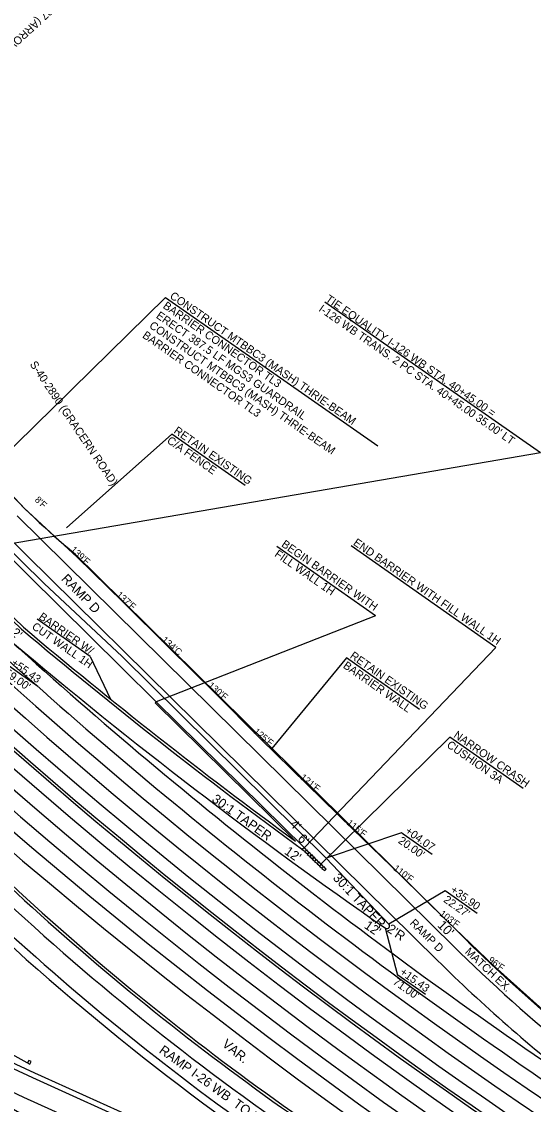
# Model space of a CAD drawing. Extents: x 1966090 to 1975830, y 788086 to 801233.
# Drawn here: x 1971783 to 1972167, y 795066 to 795878 of the extents above; entities that cross this region are included whole.
import ezdxf

# ---------------------------------------------------------------- set-up
doc = ezdxf.new("R2010")
doc.units = 0
for name, color, linetype in [('BR_PRESTRESSED BEAM', 7, 'Continuous'), ('BR_PROPOSED_DRAINAGE', 7, 'Continuous'), ('BR_REBAR', 7, 'Continuous'), ('RD_EX_Driveway_txCode', 7, 'Continuous'), ('RD_EX_RW_TX', 7, 'Continuous'), ('RD_EX_SU_Gas', 7, 'Continuous'), ('RD_EX_TX_BldgApp_ELEV', 7, 'Continuous'), ('RD_PD_PaveShd', 7, 'Continuous'), ('RD_Sketch6', 7, 'Continuous'), ('RD_Sketch8', 7, 'Continuous'), ('RD_Sketch9', 7, 'Continuous')]:
    doc.layers.add(name, color=color, linetype=linetype)

msp = doc.modelspace()

# ---------------------------------------------------------------- linework, layer by layer
at = {"layer": 'BR_PRESTRESSED BEAM'}
for p, q in [((1971761.39, 795488.77), (1971857.56, 795393.97)), ((1971857.56, 795393.97), (1971883.91, 795367.99)), ((1971754.15, 795115.72), (1971789.19, 795096.44)), ((1971788.4, 795099.15), (1971787.44, 795097.4)), ((1971787.44, 795097.4), (1971789.19, 795096.44)), ((1971790.16, 795098.19), (1971788.4, 795099.15)), ((1971789.19, 795096.44), (1971790.16, 795098.19))]:
    msp.add_line(p, q, dxfattribs=at)
msp.add_arc((1974992.33, 801056.5), 6801.99, 241.404455, 242.138411, dxfattribs=at)
at = {"layer": 'BR_PROPOSED_DRAINAGE'}
for p, q in [((1971750.82, 795549.37), (1971784.46, 795513.22)), ((1971784.46, 795513.22), (1971824.63, 795476.36)), ((1971824.63, 795476.36), (1971859.04, 795442.54)), ((1971859.04, 795442.54), (1971893.38, 795408.54)), ((1971893.38, 795408.54), (1971927.96, 795374.68)), ((1971927.96, 795374.68), (1971962.17, 795340.2)), ((1971962.17, 795340.2), (1971996.9, 795306.17)), ((1971996.9, 795306.17), (1972031.75, 795272.09)), ((1972031.75, 795272.09), (1972066.86, 795238.09)), ((1972066.86, 795238.09), (1972101.92, 795203.77)), ((1972101.92, 795203.77), (1972137.41, 795169.72)), ((1972137.41, 795169.72), (1972174.03, 795136.99))]:
    msp.add_line(p, q, dxfattribs=at)
at = {"layer": 'BR_REBAR'}
for p, q in [((1971883.91, 795367.99), (1971883.12, 795367.19)), ((1971883.12, 795367.19), (1971988.43, 795263.39)), ((1971883.91, 795367.99), (1971994.91, 795258.58))]:
    msp.add_line(p, q, dxfattribs=at)
for centre, radius, start, end in [((1974398.08, 798103.05), 3745.03, 220.92379, 225.70896), ((1974398.08, 798103.05), 3743.03, 220.92379, 225.70786), ((1974194.95, 798281.36), 3740.57, 229.84701, 233.95222), ((1974194.95, 798281.36), 3738.57, 229.84811, 233.82837)]:
    msp.add_arc(centre, radius, start, end, dxfattribs=at)
at = {"layer": 'RD_EX_SU_Gas'}
for radius, start, end in [(3784.72, 216.39766, 236.97136), (3796.72, 216.39766, 236.97136), (3842.72, 216.39766, 244.09898), (3854.72, 216.39766, 243.9112), (3866.72, 216.9932, 243.9112), (3772.72, 227.89927, 236.25939)]:
    msp.add_arc((1974296, 798203.94), radius, start, end, dxfattribs=at)
at = {"layer": 'RD_EX_TX_BldgApp_ELEV'}
for p, q in [((1971995.02, 795258.7), (1971993.5, 795257.12)), ((1971993.5, 795257.12), (1971995.59, 795255.61)), ((1971996.6, 795256.66), (1971995.02, 795258.7)), ((1971996.86, 795256.92), (1971995.34, 795255.35)), ((1971995.59, 795255.61), (1971996.6, 795256.66)), ((1971998.44, 795254.88), (1971996.86, 795256.92)), ((1971995.34, 795255.35), (1971997.43, 795253.83)), ((1971998.7, 795255.15), (1971997.17, 795253.57)), ((1971997.17, 795253.57), (1971999.26, 795252.06)), ((1971997.43, 795253.83), (1971998.44, 795254.88)), ((1972000.28, 795253.11), (1971998.7, 795255.15)), ((1972000.53, 795253.37), (1971999.01, 795251.8)), ((1971999.01, 795251.8), (1972001.1, 795250.28)), ((1971999.26, 795252.06), (1972000.28, 795253.11)), ((1972002.12, 795251.33), (1972000.53, 795253.37)), ((1972002.37, 795251.59), (1972000.85, 795250.02)), ((1972000.85, 795250.02), (1972002.94, 795248.51)), ((1972001.1, 795250.28), (1972002.12, 795251.33)), ((1972001.61, 795250.81), (1972001.61, 795250.81)), ((1972003.95, 795249.56), (1972002.37, 795251.59)), ((1972004.21, 795249.82), (1972002.69, 795248.24)), ((1972002.69, 795248.24), (1972004.78, 795246.73)), ((1972002.94, 795248.51), (1972003.95, 795249.56)), ((1972005.79, 795247.78), (1972004.21, 795249.82)), ((1972006.05, 795248.04), (1972004.52, 795246.47)), ((1972004.78, 795246.73), (1972005.79, 795247.78)), ((1972007.63, 795246), (1972006.05, 795248.04)), ((1972004.52, 795246.47), (1972006.61, 795244.95)), ((1972007.88, 795246.27), (1972006.36, 795244.69)), ((1972006.36, 795244.69), (1972008.45, 795243.18)), ((1972006.61, 795244.95), (1972007.63, 795246)), ((1972009.47, 795244.23), (1972007.88, 795246.27)), ((1972009.72, 795244.49), (1972008.2, 795242.91)), ((1972008.2, 795242.91), (1972010.29, 795241.4)), ((1972008.45, 795243.18), (1972009.47, 795244.23)), ((1972011.3, 795242.45), (1972009.72, 795244.49)), ((1972010.29, 795241.4), (1972011.3, 795242.45))]:
    msp.add_line(p, q, dxfattribs=at)
at = {"layer": 'RD_PD_PaveShd'}
for p, q in [((1971764.19, 795491.62), (1971799.86, 795456.47)), ((1972114.81, 795190.94), (1971822.32, 795479.26)), ((1971799.86, 795456.47), (1971858.24, 795401.73)), ((1971858.24, 795401.73), (1972011.44, 795250.71)), ((1972011.44, 795250.71), (1972058.4, 795201.23)), ((1971792.63, 795089.9), (1972007.59, 794992.91))]:
    msp.add_line(p, q, dxfattribs=at)
for centre, radius, start, end in [((1974398.08, 798103.05), 3745.03, 220.92379, 225.70896), ((1974296, 798203.94), 3820.72, 222.66541, 243.9112), ((1974296, 798203.94), 3818.72, 222.66592, 243.9112), ((1972190.25, 795924.25), 577.4, 222.50253, 230.41518), ((1972046.23, 795651.96), 616.62, 200.44761, 245.71509), ((1974194.95, 798281.36), 3740.57, 229.84701, 233.95222), ((1974194.95, 798281.36), 3752.57, 229.84039, 235.24659), ((1973117.1, 796675.98), 1974, 226.17145, 241.02073), ((1973117.1, 796675.98), 1972, 226.17145, 241.02073), ((1973117.1, 796675.98), 2006, 226.17145, 236.56111), ((1972056.96, 795199.85), 2, 235.24659, 55.24659), ((1972996.53, 796085.43), 1256, 225.41147, 239.13377)]:
    msp.add_arc(centre, radius, start, end, dxfattribs=at)
at = {"layer": 'RD_Sketch6'}
for p, q in [((1971890.82, 795670.85), (1971732.93, 795516)), ((1971890.82, 795670.85), (1972050.12, 795559.71)), ((1972010.36, 795667.58), (1972172.12, 795554.73)), ((1971678.64, 795470.16), (1972172.12, 795554.73)), ((1972048.37, 795432.27), (1971974.31, 795484.28)), ((1972138.59, 795408.49), (1972030.08, 795484.68)), ((1971834.36, 795401.83), (1971794.56, 795429.78)), ((1972048.37, 795432.27), (1971883.91, 795367.99)), ((1971834.36, 795401.83), (1971849.7, 795369.89)), ((1972138.59, 795408.49), (1971995.3, 795258.99)), ((1971795.19, 795379.39), (1971773.59, 795394.56)), ((1972090.79, 795253.49), (1972069.24, 795268.69)), ((1972124.77, 795209.27), (1972103.21, 795224.48)), ((1972085.82, 795148.43), (1972065.26, 795162.94))]:
    msp.add_line(p, q, dxfattribs=at)
for points in [[(1971950.53, 795529.89), (1971895.7, 795568.58), (1971816.46, 795498.27)], [(1972081.51, 795362.12), (1972026.68, 795400.82), (1971970.6, 795332.82)], [(1972159.06, 795302.81), (1972104.23, 795341.51), (1972007.54, 795246.47)], [(1972069.24, 795268.69), (1972067.92, 795269.62), (1972011.44, 795250.71)], [(1972103.21, 795224.48), (1972100.62, 795226.3), (1972058.4, 795201.23)], [(1972065.26, 795162.94), (1972065.27, 795162.89), (1972055.82, 795198.2)]]:
    msp.add_lwpolyline(points, dxfattribs=at)
at = {"layer": 'RD_Sketch8'}
for p, q in [((1971779.64, 795507.29), (1972107.79, 795183.82)), ((1972094.93, 795174.03), (1971768.41, 795495.9)), ((1971790.98, 795086.26), (1972145.53, 794926.28)), ((1971784.4, 795071.67), (1972138.95, 794911.7))]:
    msp.add_line(p, q, dxfattribs=at)
for centre, radius, start, end in [((1974296, 798203.94), 3808.72, 216.39766, 236.97136), ((1974296, 798203.94), 3830.72, 216.39766, 243.9112), ((1972046.23, 795651.96), 636.62, 156.21044, 245.71509), ((1974296, 798203.94), 3878.72, 216.39766, 241.30888), ((1972046.23, 795651.96), 620.62, 156.21044, 245.71509), ((1974296, 798203.94), 3760.72, 227.90275, 236.17378), ((1973117.1, 796675.98), 1984, 226.17145, 243.9112), ((1973117.1, 796675.98), 2000, 226.17145, 241.45743), ((1972948.57, 796040.02), 1200, 225.41147, 237.12717), ((1972948.57, 796040.02), 1216, 225.41147, 232.15338)]:
    msp.add_arc(centre, radius, start, end, dxfattribs=at)
at = {"layer": 'RD_Sketch9'}
for radius in [1974, 1972]:
    msp.add_arc((1973117.1, 796675.98), radius, 226.17145, 241.02073, dxfattribs=at)

# ---------------------------------------------------------------- texts
at = {"layer": 'RD_EX_Driveway_txCode'}
for s, height, rotation, p in [('S-40-287 (ARROWWOOD ROAD)', 5.9996, 222.69822, (1971820.63, 795905.2)), ('S-40-2890 (GRACERN ROAD)', 5.9996, 304.02477, (1971788.75, 795620.83)), ('RAMP D', 7, 314.2929, (1971812.25, 795459.58)), ("12'", 7, 318.30264, (1971770.47, 795422.27)), ('30:1 TAPER', 7, 324.52757, (1971925.04, 795293.55)), ("4'", 7, 315.41147, (1971983.57, 795275.51)), ("6'", 7, 315.41147, (1971989.5, 795264.71)), ("12'", 7, 325.47465, (1971979.49, 795254.34)), ('30:1 TAPER', 7, 313.41036, (1972015.99, 795235.45)), ("12'", 7, 325.47465, (1972039.36, 795198.78)), ("2'R", 7, 325.47465, (1972056.37, 795196.12)), ('RAMP D', 6, 315.35375, (1972073.69, 795201.61)), ("10'", 7, 315.01712, (1972094.39, 795199.92)), ('MATCH EX.', 6, 316.88876, (1972115.06, 795179.9)), (' RAMP I-26 WB  TO I-126 EB', 7, 324.11706, (1971883.37, 795106.88)), ('VAR.', 7, 320.55794, (1971932.77, 795110.37))]:
    msp.add_text(s, height=height, rotation=rotation, dxfattribs=at).set_placement(p)
at = {"layer": 'RD_EX_RW_TX'}
for s, rotation, p in [("8'F", 317.07136, (1971792.37, 795518.72)), ("139'F", 317.82136, (1971819.23, 795481.26)), ("137'F", 318.57136, (1971853.58, 795447.37)), ("134'C", 319.32136, (1971887.57, 795413.53)), ("130'F", 320.07136, (1971922.37, 795379.36)), ("125'F", 320.82136, (1971956.51, 795344.81)), ("121'F", 321.57136, (1971991.56, 795310.4)), ("115'F", 322.32136, (1972026.36, 795276.25)), ("110'F", 323.07136, (1972061.41, 795242.19)), ("103'F", 323.82136, (1972096.04, 795208.07)), ("96'F", 324.57136, (1972132.49, 795173.22))]:
    msp.add_text(s, height=5, rotation=rotation, dxfattribs=at).set_placement(p)
at = {"layer": 'RD_Sketch6'}
for s, height, rotation, p in [('CONSTRUCT MTBBC3 (MASH) THRIE-BEAM', 5.9996, 325.12415, (1971893.58, 795670.8)), ('TIE EQUALITY I-126 WB STA. 40+45.00 =', 5.9996, 325.17378, (1972010.4, 795668.48)), ('BARRIER CONNECTOR TL3', 5.9996, 325.12415, (1971888.44, 795663.42)), ("I-126 WB TRANS. 2 PC STA. 40+45.00 35.00' LT", 5.9996, 325.17378, (1972005.26, 795661.1)), ('ERECT 387.5 LF MGS3 GUARDRAIL', 5.9996, 325.12415, (1971883.29, 795656.04)), ('BARRIER CONNECTOR TL3', 5.9996, 325.12415, (1971873, 795641.27)), ('CONSTRUCT MTBBC3 (MASH) THRIE-BEAM', 5.9996, 325.12415, (1971878.14, 795648.65)), ('RETAIN EXISTING', 5.9996, 325.08336, (1971896.56, 795569.81)), ('C/A FENCE', 6, 325.08336, (1971891.41, 795562.43)), ('BEGIN BARRIER WITH', 5.9996, 325.08336, (1971977.3, 795484.75)), ('END BARRIER WITH FILL WALL 1H', 5.9996, 325.08336, (1972031.21, 795485.89)), ('FILL WALL 1H', 5.9996, 325.08336, (1971972.15, 795477.37)), ('BARRIER W/', 6, 325.08336, (1971795.22, 795430.38)), ('CUT WALL 1H', 5.9996, 325.08336, (1971790.06, 795423)), ('RETAIN EXISTING', 5.9996, 325.08336, (1972028.71, 795401.16)), ('+55.43', 6, 324.92357, (1971774.46, 795395.79)), ('BARRIER WALL', 5.9996, 325.08336, (1972023.56, 795393.78)), ("59.00'", 6, 324.92357, (1971769.28, 795388.42)), ('NARROW CRASH', 5.9996, 325.08336, (1972106.48, 795341.7)), ('CUSHION 3A', 6, 325.08336, (1972101.33, 795334.32)), ('+04.07', 6, 324.80586, (1972070.1, 795269.91)), ("20.00'", 6, 324.80586, (1972064.92, 795262.56)), ('+35.90', 6, 324.80586, (1972104.07, 795225.7)), ("22.27'", 6, 324.80586, (1972098.88, 795218.35)), ('+15.43', 6, 324.80586, (1972066.12, 795164.16)), ("71.00'", 6, 324.80586, (1972060.94, 795156.81))]:
    msp.add_text(s, height=height, rotation=rotation, dxfattribs=at).set_placement(p)

doc.saveas('drawing.dxf')
